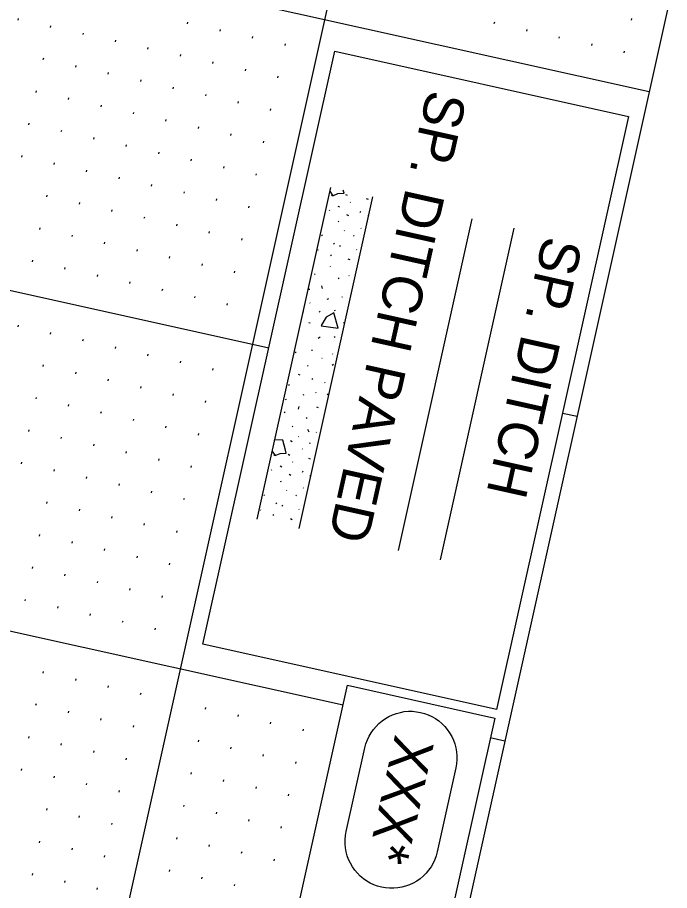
# Model space of a CAD drawing. Extents: x 2149268 to 2150830, y 142155 to 144285.
# Drawn here: x 2149865 to 2149963, y 142636.2 to 142767.5 of the extents above; entities that cross this region are included whole.
import ezdxf

# ---------------------------------------------------------------- set-up
doc = ezdxf.new("R2010")
doc.units = 0
for name, color, linetype in [('PR_Grading_Txt', 7, 'Continuous'), ('PR_Misc_Improvement', 7, 'Continuous'), ('PR_Storm_Ditch_Paved', 7, 'Continuous'), ('PR_Storm_Ditch_Special', 7, 'Continuous'), ('PR_Storm_Txt_PH1B', 7, 'Continuous'), ('SHT_Profile_Grid_Major', 7, 'Continuous'), ('SHT_Profile_Grid_Minor', 7, 'Continuous'), ('SHT_Sheet_Border', 7, 'Continuous')]:
    doc.layers.add(name, color=color, linetype=linetype)

msp = doc.modelspace()

# ---------------------------------------------------------------- linework, layer by layer
at = {"layer": 'PR_Misc_Improvement'}
for points in [[(2149956.83, 142752.56), (2149937.01, 142663.43), (2149892.87, 142673.25), (2149912.69, 142762.37)], [(2149936.73, 142662.14), (2149902.85, 142509.8), (2149880.72, 142514.72), (2149914.6, 142667.07)]]:
    msp.add_lwpolyline(points, close=True, dxfattribs=at)
at = {"layer": 'PR_Storm_Ditch_Paved'}
for p, q in [((2149912.33, 142740.73), (2149912.2, 142740.65)), ((2149914.62, 142740.67), (2149914.36, 142740.78)), ((2149915.05, 142739.62), (2149915.01, 142739.69)), ((2149917.74, 142740.09), (2149917.48, 142740.2)), ((2149911.93, 142738.41), (2149911.88, 142738.48)), ((2149913.44, 142738.92), (2149913.19, 142739.03)), ((2149914.79, 142737.66), (2149914.53, 142737.78)), ((2149916.55, 142738.28), (2149916.45, 142738.08)), ((2149910.98, 142736.94), (2149910.95, 142736.95)), ((2149913.2, 142736.84), (2149913.29, 142736.71)), ((2149917.65, 142737.7), (2149917.74, 142737.57)), ((2149914.17, 142735.39), (2149914.13, 142735.45)), ((2149916.66, 142735.74), (2149916.62, 142735.8)), ((2149910.72, 142734.76), (2149910.81, 142734.63)), ((2149915.53, 142734.7), (2149915.61, 142734.57)), ((2149912.52, 142733.52), (2149912.6, 142733.38)), ((2149913.55, 142733.12), (2149913.42, 142733.03)), ((2149916, 142732.52), (2149915.96, 142732.58)), ((2149910.26, 142732.45), (2149910.22, 142732.51)), ((2149912.07, 142731.76), (2149912.16, 142731.63)), ((2149912.07, 142729.97), (2149912.03, 142730.04)), ((2149914.99, 142731.01), (2149914.73, 142731.12)), ((2149909.65, 142728.94), (2149909.74, 142728.81)), ((2149914.85, 142728.63), (2149914.81, 142728.69)), ((2149913.21, 142728.32), (2149913.3, 142728.19)), ((2149908.96, 142726.57), (2149908.73, 142726.56)), ((2149910.71, 142727.13), (2149910.78, 142726.72)), ((2149911.73, 142725.17), (2149911.48, 142725.06)), ((2149913.85, 142725.37), (2149913.81, 142725.44)), ((2149909, 142724.49), (2149908.96, 142724.55)), ((2149912.74, 142723.43), (2149912.61, 142723.35)), ((2149907.98, 142723.2), (2149907.88, 142723.13)), ((2149910.36, 142723.29), (2149910.44, 142723.16)), ((2149909.01, 142721.51), (2149908.8, 142721.56)), ((2149914.13, 142721.61), (2149914, 142721.52)), ((2149910.19, 142719.23), (2149910.51, 142719.44)), ((2149912.59, 142719.48), (2149912.68, 142719.35)), ((2149906.76, 142717.19), (2149906.84, 142717.06)), ((2149909.24, 142717.48), (2149909.27, 142717.36)), ((2149912.4, 142716.84), (2149912.36, 142716.9)), ((2149910.8, 142716.2), (2149910.73, 142716.17)), ((2149908.71, 142715.13), (2149908.58, 142715.05)), ((2149912.51, 142715.3), (2149912.3, 142715.12)), ((2149907.49, 142713.67), (2149907.24, 142713.78)), ((2149909.39, 142713.13), (2149909.26, 142713.05)), ((2149905.84, 142712.3), (2149905.74, 142712.09)), ((2149911.26, 142712.49), (2149911.22, 142712.56)), ((2149907.92, 142710.82), (2149908.01, 142710.69)), ((2149909.79, 142711.14), (2149909.87, 142711.01)), ((2149911.68, 142710.83), (2149911.55, 142710.74)), ((2149905.39, 142710.04), (2149905.26, 142709.96)), ((2149907.25, 142708.56), (2149907.35, 142708.99)), ((2149905.25, 142708.11), (2149905.11, 142708.03)), ((2149910.27, 142708.79), (2149910.01, 142708.85)), ((2149908.53, 142707.27), (2149908.4, 142707.18)), ((2149906.3, 142706.03), (2149906.38, 142705.9)), ((2149908.84, 142705.12), (2149908.65, 142705.5)), ((2149909.94, 142705.05), (2149909.9, 142705.11)), ((2149906.28, 142703.68), (2149906.02, 142703.79)), ((2149907.28, 142704.41), (2149907.24, 142704.47)), ((2149907.82, 142702.55), (2149907.78, 142702.61)), ((2149908.88, 142703.55), (2149908.97, 142703.42)), ((2149903.65, 142701.69), (2149903.52, 142701.6)), ((2149905.93, 142701.63), (2149905.68, 142701.74)), ((2149909.06, 142701.05), (2149908.8, 142701.16)), ((2149904.76, 142699.87), (2149904.5, 142699.98)), ((2149906.37, 142700.58), (2149906.33, 142700.64)), ((2149903.24, 142699.37), (2149903.2, 142699.43)), ((2149906.11, 142698.62), (2149905.85, 142698.73)), ((2149907.87, 142699.23), (2149907.77, 142699.03)), ((2149908.97, 142698.65), (2149909.06, 142698.52)), ((2149902.3, 142697.89), (2149902.27, 142697.91)), ((2149904.52, 142697.79), (2149904.6, 142697.66)), ((2149905.49, 142696.34), (2149905.45, 142696.41)), ((2149907.98, 142696.69), (2149907.93, 142696.75)), ((2149902.04, 142695.71), (2149902.12, 142695.58)), ((2149903.84, 142694.47), (2149903.92, 142694.34)), ((2149906.85, 142695.65), (2149906.93, 142695.52)), ((2149901.58, 142693.4), (2149901.54, 142693.46)), ((2149904.87, 142694.07), (2149904.74, 142693.99)), ((2149907.32, 142693.47), (2149907.27, 142693.54)), ((2149903.39, 142692.72), (2149903.48, 142692.59)), ((2149906.31, 142691.96), (2149906.05, 142692.07))]:
    msp.add_line(p, q, dxfattribs=at)
for points in [[(2149911.93, 142741.36), (2149912.39, 142740.66), (2149913.17, 142740.97), (2149914.1, 142741.03), (2149913.98, 142741.48)], [(2149910.67, 142721.11), (2149913.21, 142720.73), (2149912.56, 142723.07), (2149911.41, 142722.39), (2149910.65, 142721.13)], [(2149905.3, 142702.43), (2149904.91, 142703.93), (2149903.67, 142703.96), (2149903.6, 142703.88)], [(2149903.25, 142702.31), (2149903.71, 142701.61), (2149904.48, 142701.92), (2149905.41, 142701.98), (2149905.3, 142702.43)]]:
    msp.add_lwpolyline(points, dxfattribs=at)
at = {"layer": 'PR_Storm_Ditch_Special'}
for p, q in [((2149912.06, 142741.91), (2149900.97, 142692.05)), ((2149918.39, 142740.5), (2149907.3, 142690.64)), ((2149933.29, 142737.19), (2149922.2, 142687.33)), ((2149939.62, 142735.78), (2149928.54, 142685.92))]:
    msp.add_line(p, q, dxfattribs=at)
at = {"layer": 'PR_Storm_Txt_PH1B'}
for points in [[(2149917.23, 142657.67), (2149917.38, 142658.26), (2149917.59, 142658.84), (2149917.85, 142659.39), (2149918.16, 142659.92), (2149918.51, 142660.42), (2149918.9, 142660.89), (2149919.33, 142661.32), (2149919.8, 142661.71), (2149920.3, 142662.06), (2149920.83, 142662.37), (2149921.38, 142662.62), (2149921.96, 142662.83), (2149922.55, 142662.99), (2149923.15, 142663.1), (2149923.76, 142663.15), (2149924.37, 142663.15), (2149924.98, 142663.09), (2149925.58, 142662.99), (2149925.58, 142662.99), (2149926.17, 142662.83), (2149926.74, 142662.62), (2149927.29, 142662.36), (2149927.82, 142662.06), (2149928.32, 142661.71), (2149928.79, 142661.31), (2149929.22, 142660.88), (2149929.61, 142660.41), (2149929.96, 142659.91), (2149930.27, 142659.38), (2149930.53, 142658.83), (2149930.74, 142658.26), (2149930.89, 142657.67), (2149931, 142657.06), (2149931.05, 142656.46), (2149931.05, 142655.85), (2149931, 142655.24), (2149930.89, 142654.64)], [(2149914.42, 142645.06), (2149917.23, 142657.67)], [(2149930.89, 142654.64), (2149928.09, 142642.02)], [(2149928.09, 142642.02), (2149927.93, 142641.43), (2149927.72, 142640.86), (2149927.46, 142640.31), (2149927.16, 142639.78), (2149926.8, 142639.28), (2149926.41, 142638.81), (2149925.98, 142638.38), (2149925.51, 142637.99), (2149925.01, 142637.64), (2149924.48, 142637.33), (2149923.93, 142637.07), (2149923.35, 142636.86), (2149922.76, 142636.71), (2149922.16, 142636.6), (2149921.55, 142636.55), (2149920.94, 142636.55), (2149920.34, 142636.6), (2149919.73, 142636.71), (2149919.73, 142636.71), (2149919.14, 142636.87), (2149918.57, 142637.08), (2149918.02, 142637.33), (2149917.49, 142637.64), (2149916.99, 142637.99), (2149916.52, 142638.38), (2149916.09, 142638.82), (2149915.7, 142639.28), (2149915.35, 142639.78), (2149915.04, 142640.31), (2149914.78, 142640.87), (2149914.58, 142641.44), (2149914.42, 142642.03), (2149914.31, 142642.63), (2149914.26, 142643.24), (2149914.26, 142643.85), (2149914.31, 142644.46), (2149914.42, 142645.06)]]:
    msp.add_lwpolyline(points, dxfattribs=at)
at = {"layer": 'SHT_Profile_Grid_Major'}
for p, q in [((2150158.06, 143877.55), (2149816.2, 142340.1)), ((2149471.89, 142864.84), (2149959.97, 142756.31)), ((2149461.04, 142816.03), (2149902.78, 142717.81)), ((2149450.18, 142767.23), (2149913.94, 142664.11)), ((2149946.92, 142707.99), (2149949.12, 142707.51)), ((2149936.07, 142659.19), (2149938.26, 142658.7))]:
    msp.add_line(p, q, dxfattribs=at)
at = {"layer": 'SHT_Profile_Grid_Minor'}
for p, q in [((2149865.09, 142767.3), (2149865.04, 142767.05)), ((2149890.58, 142766.75), (2149890.53, 142766.51)), ((2149936.68, 142766.74), (2149936.62, 142766.5)), ((2149957.29, 142767.28), (2149957.23, 142767.04)), ((2149869.97, 142766.21), (2149869.92, 142765.97)), ((2149895.46, 142765.66), (2149895.41, 142765.42)), ((2149941.56, 142765.66), (2149941.5, 142765.41)), ((2149874.85, 142765.12), (2149874.8, 142764.88)), ((2149879.73, 142764.04), (2149879.68, 142763.8)), ((2149900.34, 142764.58), (2149900.29, 142764.34)), ((2149946.44, 142764.57), (2149946.38, 142764.33)), ((2149884.61, 142762.95), (2149884.56, 142762.71)), ((2149905.22, 142763.49), (2149905.17, 142763.25)), ((2149951.32, 142763.49), (2149951.27, 142763.24)), ((2149889.49, 142761.87), (2149889.44, 142761.62)), ((2149956.2, 142762.4), (2149956.15, 142762.16)), ((2149868.89, 142761.33), (2149868.83, 142761.09)), ((2149873.77, 142760.24), (2149873.71, 142760)), ((2149894.37, 142760.78), (2149894.32, 142760.54)), ((2149878.65, 142759.16), (2149878.59, 142758.91)), ((2149899.26, 142759.7), (2149899.2, 142759.45)), ((2149883.53, 142758.07), (2149883.47, 142757.83)), ((2149904.14, 142758.61), (2149904.08, 142758.37)), ((2149867.8, 142756.45), (2149867.75, 142756.2)), ((2149888.41, 142756.99), (2149888.35, 142756.74)), ((2149872.68, 142755.36), (2149872.63, 142755.12)), ((2149893.29, 142755.9), (2149893.24, 142755.66)), ((2149877.56, 142754.28), (2149877.51, 142754.03)), ((2149898.17, 142754.82), (2149898.12, 142754.57)), ((2149903.05, 142753.73), (2149903, 142753.49)), ((2149882.44, 142753.19), (2149882.39, 142752.95)), ((2149866.72, 142751.57), (2149866.66, 142751.32)), ((2149887.32, 142752.11), (2149887.27, 142751.86)), ((2149892.2, 142751.02), (2149892.15, 142750.78)), ((2149871.6, 142750.48), (2149871.54, 142750.24)), ((2149897.09, 142749.94), (2149897.03, 142749.69)), ((2149876.48, 142749.4), (2149876.42, 142749.15)), ((2149881.36, 142748.31), (2149881.3, 142748.07)), ((2149901.97, 142748.85), (2149901.91, 142748.61)), ((2149886.24, 142747.23), (2149886.18, 142746.98)), ((2149865.63, 142746.69), (2149865.58, 142746.44)), ((2149891.12, 142746.14), (2149891.06, 142745.9)), ((2149870.51, 142745.6), (2149870.46, 142745.36)), ((2149875.39, 142744.52), (2149875.34, 142744.27)), ((2149896, 142745.06), (2149895.95, 142744.81)), ((2149880.27, 142743.43), (2149880.22, 142743.19)), ((2149900.88, 142743.97), (2149900.83, 142743.73)), ((2149885.15, 142742.35), (2149885.1, 142742.1)), ((2149869.43, 142740.72), (2149869.37, 142740.48)), ((2149890.03, 142741.26), (2149889.98, 142741.02)), ((2149874.31, 142739.64), (2149874.25, 142739.39)), ((2149894.91, 142740.18), (2149894.86, 142739.93)), ((2149899.8, 142739.09), (2149899.74, 142738.85)), ((2149879.19, 142738.55), (2149879.13, 142738.31)), ((2149884.07, 142737.46), (2149884.01, 142737.22)), ((2149868.34, 142735.84), (2149868.29, 142735.6)), ((2149888.95, 142736.38), (2149888.89, 142736.14)), ((2149893.83, 142735.29), (2149893.78, 142735.05)), ((2149873.22, 142734.75), (2149873.17, 142734.51)), ((2149898.71, 142734.21), (2149898.66, 142733.97)), ((2149878.1, 142733.67), (2149878.05, 142733.43)), ((2149882.98, 142732.58), (2149882.93, 142732.34)), ((2149887.86, 142731.5), (2149887.81, 142731.25)), ((2149867.25, 142730.96), (2149867.2, 142730.72)), ((2149892.74, 142730.41), (2149892.69, 142730.17)), ((2149872.14, 142729.87), (2149872.08, 142729.63)), ((2149877.02, 142728.79), (2149876.96, 142728.54)), ((2149897.62, 142729.33), (2149897.57, 142729.08)), ((2149881.9, 142727.7), (2149881.84, 142727.46)), ((2149886.78, 142726.62), (2149886.72, 142726.37)), ((2149891.66, 142725.53), (2149891.6, 142725.29)), ((2149896.54, 142724.45), (2149896.49, 142724.2)), ((2149865.08, 142721.2), (2149865.03, 142720.95)), ((2149869.97, 142720.11), (2149869.91, 142719.87)), ((2149874.85, 142719.03), (2149874.79, 142718.78)), ((2149879.73, 142717.94), (2149879.67, 142717.7)), ((2149884.61, 142716.86), (2149884.55, 142716.61)), ((2149889.49, 142715.77), (2149889.43, 142715.53)), ((2149868.88, 142715.23), (2149868.83, 142714.99)), ((2149873.76, 142714.15), (2149873.71, 142713.9)), ((2149894.37, 142714.69), (2149894.31, 142714.44)), ((2149878.64, 142713.06), (2149878.59, 142712.82)), ((2149883.52, 142711.98), (2149883.47, 142711.73)), ((2149867.79, 142710.35), (2149867.74, 142710.11)), ((2149888.4, 142710.89), (2149888.35, 142710.65)), ((2149872.68, 142709.27), (2149872.62, 142709.02)), ((2149893.28, 142709.81), (2149893.23, 142709.56)), ((2149877.56, 142708.18), (2149877.5, 142707.94)), ((2149882.44, 142707.09), (2149882.38, 142706.85)), ((2149866.71, 142705.47), (2149866.65, 142705.23)), ((2149887.32, 142706.01), (2149887.26, 142705.77)), ((2149871.59, 142704.38), (2149871.54, 142704.14)), ((2149892.2, 142704.92), (2149892.14, 142704.68)), ((2149876.47, 142703.3), (2149876.42, 142703.06)), ((2149881.35, 142702.21), (2149881.3, 142701.97)), ((2149886.23, 142701.13), (2149886.18, 142700.88)), ((2149865.62, 142700.59), (2149865.57, 142700.35)), ((2149891.11, 142700.04), (2149891.06, 142699.8)), ((2149870.5, 142699.5), (2149870.45, 142699.26)), ((2149875.39, 142698.42), (2149875.33, 142698.17)), ((2149880.27, 142697.33), (2149880.21, 142697.09)), ((2149885.15, 142696.25), (2149885.09, 142696)), ((2149869.42, 142694.62), (2149869.37, 142694.38)), ((2149890.03, 142695.16), (2149889.97, 142694.92)), ((2149874.3, 142693.54), (2149874.25, 142693.29)), ((2149879.18, 142692.45), (2149879.13, 142692.21)), ((2149884.06, 142691.37), (2149884.01, 142691.12)), ((2149868.33, 142689.74), (2149868.28, 142689.5)), ((2149888.94, 142690.28), (2149888.89, 142690.04)), ((2149873.21, 142688.66), (2149873.16, 142688.41)), ((2149878.1, 142687.57), (2149878.04, 142687.33)), ((2149882.98, 142686.49), (2149882.92, 142686.24)), ((2149887.86, 142685.4), (2149887.8, 142685.16)), ((2149867.25, 142684.86), (2149867.19, 142684.62)), ((2149872.13, 142683.78), (2149872.08, 142683.53)), ((2149877.01, 142682.69), (2149876.96, 142682.45)), ((2149881.89, 142681.61), (2149881.84, 142681.36)), ((2149886.77, 142680.52), (2149886.72, 142680.28)), ((2149866.16, 142679.98), (2149866.11, 142679.74)), ((2149871.04, 142678.9), (2149870.99, 142678.65)), ((2149875.93, 142677.81), (2149875.87, 142677.57)), ((2149880.81, 142676.72), (2149880.75, 142676.48)), ((2149885.69, 142675.64), (2149885.63, 142675.4)), ((2149868.87, 142669.13), (2149868.82, 142668.89)), ((2149873.75, 142668.05), (2149873.7, 142667.8)), ((2149878.64, 142666.96), (2149878.58, 142666.72)), ((2149883.52, 142665.88), (2149883.46, 142665.63)), ((2149867.79, 142664.25), (2149867.73, 142664.01)), ((2149872.67, 142663.17), (2149872.62, 142662.92)), ((2149893.28, 142663.71), (2149893.22, 142663.46)), ((2149877.55, 142662.08), (2149877.5, 142661.84)), ((2149898.16, 142662.62), (2149898.1, 142662.38)), ((2149882.43, 142661), (2149882.38, 142660.75)), ((2149903.04, 142661.54), (2149902.99, 142661.29)), ((2149907.92, 142660.45), (2149907.87, 142660.21)), ((2149866.7, 142659.37), (2149866.65, 142659.13)), ((2149871.58, 142658.29), (2149871.53, 142658.04)), ((2149892.19, 142658.83), (2149892.14, 142658.58)), ((2149897.07, 142657.74), (2149897.02, 142657.5)), ((2149876.46, 142657.2), (2149876.41, 142656.96)), ((2149901.95, 142656.66), (2149901.9, 142656.41)), ((2149881.35, 142656.12), (2149881.29, 142655.87)), ((2149906.83, 142655.57), (2149906.78, 142655.33)), ((2149865.62, 142654.49), (2149865.56, 142654.25)), ((2149891.11, 142653.95), (2149891.05, 142653.7)), ((2149870.5, 142653.41), (2149870.44, 142653.16)), ((2149895.99, 142652.86), (2149895.93, 142652.62)), ((2149875.38, 142652.32), (2149875.33, 142652.08)), ((2149880.26, 142651.24), (2149880.21, 142650.99)), ((2149900.87, 142651.78), (2149900.81, 142651.53)), ((2149905.75, 142650.69), (2149905.7, 142650.45)), ((2149869.41, 142648.53), (2149869.36, 142648.28)), ((2149890.02, 142649.06), (2149889.97, 142648.82)), ((2149874.29, 142647.44), (2149874.24, 142647.2)), ((2149894.9, 142647.98), (2149894.85, 142647.74)), ((2149879.18, 142646.35), (2149879.12, 142646.11)), ((2149899.78, 142646.89), (2149899.73, 142646.65)), ((2149904.66, 142645.81), (2149904.61, 142645.57)), ((2149868.33, 142643.64), (2149868.27, 142643.4)), ((2149888.94, 142644.18), (2149888.88, 142643.94)), ((2149873.21, 142642.56), (2149873.15, 142642.32)), ((2149893.82, 142643.1), (2149893.76, 142642.85)), ((2149898.7, 142642.01), (2149898.64, 142641.77)), ((2149878.09, 142641.47), (2149878.04, 142641.23)), ((2149903.58, 142640.93), (2149903.52, 142640.68)), ((2149867.24, 142638.76), (2149867.19, 142638.52)), ((2149887.85, 142639.3), (2149887.8, 142639.06)), ((2149892.73, 142638.22), (2149892.68, 142637.97)), ((2149872.12, 142637.68), (2149872.07, 142637.43)), ((2149897.61, 142637.13), (2149897.56, 142636.89)), ((2149877, 142636.59), (2149876.95, 142636.35))]:
    msp.add_line(p, q, dxfattribs=at)
at = {"layer": 'SHT_Sheet_Border'}
msp.add_line((2150206.87, 143866.7), (2149865.01, 142329.24), dxfattribs=at)

# ---------------------------------------------------------------- texts
at = {"layer": 'PR_Grading_Txt'}
for s, p in [('SP. DITCH PAVED', (2149926.7, 142756.78)), ('SP. DITCH', (2149944.1, 142734.8))]:
    msp.add_text(s, height=6, rotation=257.4638, dxfattribs=at).set_placement(p)
at = {"layer": 'PR_Storm_Txt_PH1B'}
msp.add_text('XXX*', height=6, rotation=257.4638, dxfattribs=at).set_placement((2149921.79, 142659.78))

doc.saveas('drawing.dxf')
